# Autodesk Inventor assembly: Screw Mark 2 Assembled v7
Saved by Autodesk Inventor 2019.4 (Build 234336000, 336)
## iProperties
Created: 2020-06
Part Number: Screw Mark 2 Assembled v7
Document SubType Name: Assembly
Designer: Administrator
Title: Screw Mark 2 Assembled v7
Author: Administrator
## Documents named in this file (15)
- c:\worker\convert-fusion-r04\tmp\job-1\85\output\files\12fc5e84-6763-4458-a53a-9d1ae2180744\Screw Mark 2 Assembled v7_1.iam
- c:\worker\convert-fusion-r04\tmp\job-1\85\output\files\12fc5e84-6763-4458-a53a-9d1ae2180744\001 Roller v3.ipt
- c:\worker\convert-fusion-r04\tmp\job-1\85\output\files\12fc5e84-6763-4458-a53a-9d1ae2180744\Upgraded Screw Harry Edited v15.ipt
- c:\worker\convert-fusion-r04\tmp\job-1\85\output\files\12fc5e84-6763-4458-a53a-9d1ae2180744\Component1_1.ipt
- c:\worker\convert-fusion-r04\tmp\job-1\85\output\files\12fc5e84-6763-4458-a53a-9d1ae2180744\Component2.ipt
- c:\worker\convert-fusion-r04\tmp\job-1\85\output\files\12fc5e84-6763-4458-a53a-9d1ae2180744\Component3.ipt
- c:\worker\convert-fusion-r04\tmp\job-1\85\output\files\12fc5e84-6763-4458-a53a-9d1ae2180744\Component4.ipt
- c:\worker\convert-fusion-r04\tmp\job-1\85\output\files\12fc5e84-6763-4458-a53a-9d1ae2180744\Component5.ipt
- c:\worker\convert-fusion-r04\tmp\job-1\85\output\files\12fc5e84-6763-4458-a53a-9d1ae2180744\Component6.ipt
- c:\worker\convert-fusion-r04\tmp\job-1\85\output\files\12fc5e84-6763-4458-a53a-9d1ae2180744\Component7.ipt
- c:\worker\convert-fusion-r04\tmp\job-1\85\output\files\12fc5e84-6763-4458-a53a-9d1ae2180744\Component8.ipt
- c:\worker\convert-fusion-r04\tmp\job-1\85\output\files\12fc5e84-6763-4458-a53a-9d1ae2180744\Component9.ipt
- c:\worker\convert-fusion-r04\tmp\job-1\85\output\files\12fc5e84-6763-4458-a53a-9d1ae2180744\Component10.ipt
- c:\worker\convert-fusion-r04\tmp\job-1\85\output\files\12fc5e84-6763-4458-a53a-9d1ae2180744\Component11.ipt
- c:\worker\convert-fusion-r04\tmp\job-1\85\output\files\12fc5e84-6763-4458-a53a-9d1ae2180744\Component12.ipt
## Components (25 placed, 14 different names)
1. 001 Roller v3:1
2. 001 Roller v3:2
3. 001 Roller v3:3
4. 001 Roller v3:4
5. 001 Roller v3:5
6. 001 Roller v3:6
7. 001 Roller v3:7
8. 001 Roller v3:8
9. 001 Roller v3:9
10. 001 Roller v3:10
11. 001 Roller v3:11
12. 001 Roller v3:12
13. Upgraded Screw Harry Edited v15:1
14. Component1:1
15. Component2:1
16. Component3:1
17. Component4:1
18. Component5:1
19. Component6:1
20. Component7:1
21. Component8:1
22. Component9:1
23. Component10:1
24. Component11:1
25. Component12:1
